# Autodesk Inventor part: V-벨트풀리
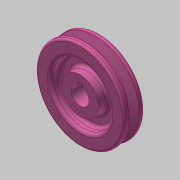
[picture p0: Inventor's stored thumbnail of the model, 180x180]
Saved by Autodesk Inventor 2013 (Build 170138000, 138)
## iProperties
Created: 2018-11
Part Number: V-벨트풀리
Material: 알루미늄 6061
Document SubType Name: Modeling
Designer: mduedu
Density: 1 g/cm^3
Author: mduedu
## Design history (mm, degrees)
sketch "스케치1"
  geometry: L1 (-9.5, 0)-(9.5, 0); L2 (9.5, 0)-(9.5, 42.7); L3 (9.5, 42.7)-(-9.5, 42.7); L4 (-9.5, 42.7)-(-9.5, 0); L5 (-4.877, 42.7)-(-1.953, 33.7); L6 (-1.953, 33.7)-(1.953, 33.7); L7 (1.953, 33.7)-(4.877, 42.7); L8 (0, 0)-(0, 42.7); L9 (-9.5, 40)-(9.5, 40); 3 further points
  constraints: 18 end point, 8 point on line, 3 perpendicular, 2 midpoint, 2 parallel, 1 coincident, 1 horizontal, 1 other
  dimensions: "d0" = 85.4 diameter of L3 L1; "d2" = 19 distance of L2.end L3.end; "d3" = 80 diameter of L9 L1; "d4" = 36 deg angle of L7 L5; "d5" = 6.3 distance between parallel lines of L6 L9; "d6" = 8 distance of point (4, 40) point (-4, 40)
revolve "회전1" sketch "스케치1" stored, may be unused: angle "d7" = 90 deg
sketch "스케치2"
  geometry: L1 (-2.5, 8.124)-(2.5, 8.124); L2 (2.5, 8.124)-(2.5, 10.8); L3 (2.5, 10.8)-(-2.5, 10.8); L4 (-2.5, 10.8)-(-2.5, 8.124); A1 r 8.5 centre (0, 0) between (-2.5, 8.124) and (2.5, 8.124); 1 further point
  constraints: 8 end point, 2 parallel, 2 point on circle, 1 centre point, 1 coincident, 1 horizontal, 1 perpendicular
  dimensions: "d8" = 17 diameter of A1; "d10" = 19.3 dimension on A1 L3; "d11" = 5 distance of L2.end L3.end
extrude "돌출1" cut sketch "스케치2" stored distance "d12" = 10; taper "d13" = 0 deg
chamfer "모따기1" distance "d14" = 1; stored, may be unused: second distance "d15" = 2, angle "d16" = 45 deg
fillet "모깎기1" dims "d17" = 1, "d18" = 0.5, "d19" = 2
sketch "스케치3"
  geometry: C1 r 17.5 at (0, 0); C2 r 28.5 at (0, 0); 1 further point
  constraints: 2 centre point, 2 coincident
  dimensions: "d20" = 35 diameter of C1; "d23" = 57 diameter of C2
extrude "돌출2" cut sketch "스케치3" distance "d24" = 9.5; taper "d25" = 0 deg
fillet "모깎기2" dims "d26" = 3
node "솔리드1"
